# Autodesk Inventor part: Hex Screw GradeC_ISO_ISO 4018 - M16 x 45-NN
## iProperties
Shininess: 64.0
Length Units: 11269
Angle Units: 11279
Time Units: 11290
Mass Units: 11283
Length Display Precision: 3
Angle Display Precision: 2
Compacted: True
Part Number: Hex Screw GradeC_ISO_ISO 4018 - M16 x 45-NN
Document SubType Name: Modeling
Created: 2006-11
Material: Par défaut
Designer: profs_sti
Density: 0.0
Volumn: 0.0
Area: 0.0
PropertySet Name: Model Information
Control State: 0
Master: False
Checked Out: False
Author: profs_sti
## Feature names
1. Base1
